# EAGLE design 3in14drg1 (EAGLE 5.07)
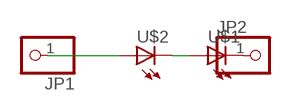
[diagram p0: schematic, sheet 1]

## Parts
JP1  PINHD-1X11X0.4  [1X01]
JP2  PINHD-1X11X0.4  [1X01]
U$1  LEDSMT1206  [1206]
U$2  LEDSMT1206  [1206]

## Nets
N$1: JP1.1 U$2.A
N$3: U$1.A U$2.C
N$4: JP2.1 U$1.C

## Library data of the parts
JP1 JP2 = pinhead:PINHD-1X1: PIN HEADER
U$1 U$2 = led(2):LED: LED

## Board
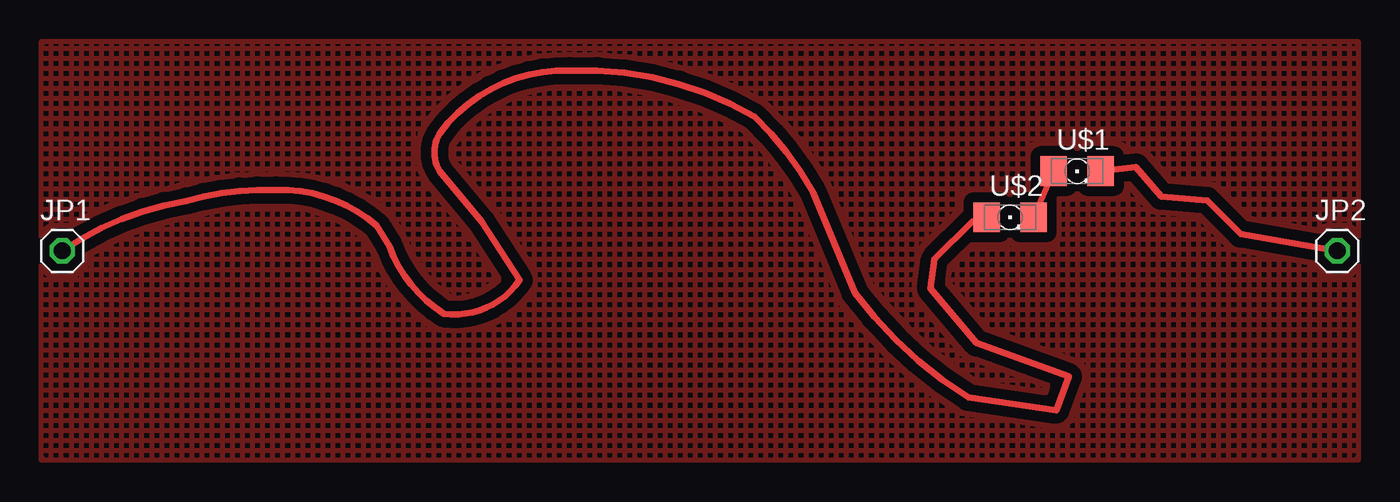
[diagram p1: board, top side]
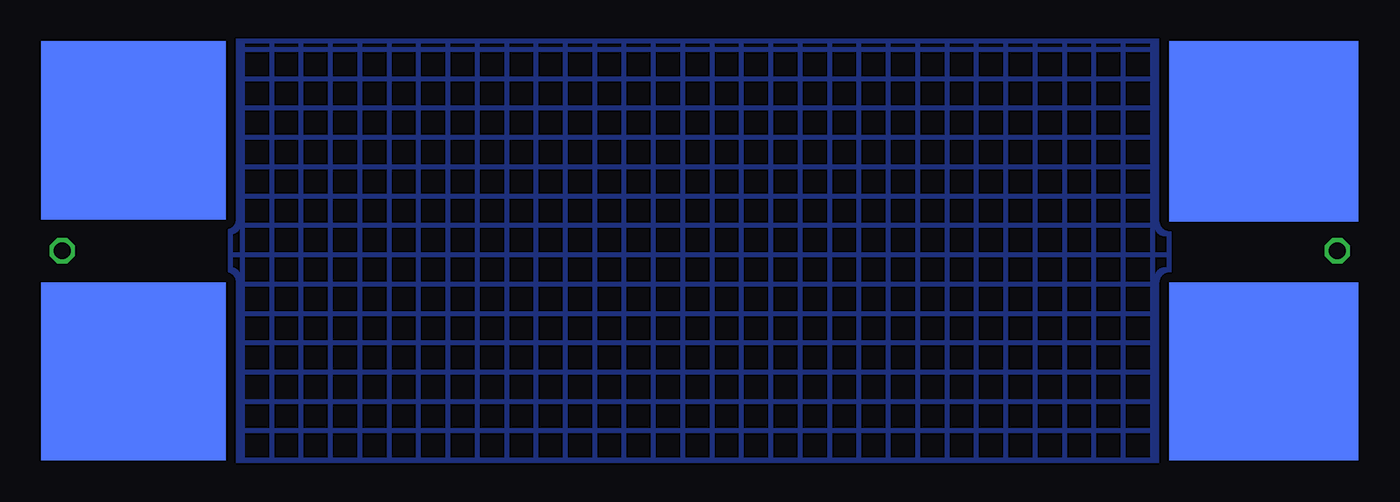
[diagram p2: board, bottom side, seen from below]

No outline drawn. Coordinates in mm, seen from the top.
Copper layers (1*16): Top 0.035mm / dielectric 1.5mm / Bottom 0.035mm
Design rules "default": minimum track width 10mil, minimum drill 24mil, track to track 8mil, track to pad 8mil, pad to pad 8mil, via to via 8mil, smd to smd 8mil, copper to edge 40mil, drill to drill 8mil, minimum pad ring 10mil, minimum via ring 8mil, stop-mask expansion 4mil, vias tented up to drill 0mil, thermal gap 10mil

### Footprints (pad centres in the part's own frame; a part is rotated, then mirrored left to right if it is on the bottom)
1X01 = drill 1.016 octagon: 1 0,0
1206 = smd 1.6 x 1.803: A -1.422,0; C 1.422,0

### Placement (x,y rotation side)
JP1  1.27,12.7 0 top
JP2  78.49,12.7 0 top
U$1  62.74,17.53 0 top
U$2  58.67,14.73 0 top

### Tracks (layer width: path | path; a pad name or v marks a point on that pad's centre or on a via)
N$1
  Top 0.406: JP1.1 arc-25 8.79,15.72 arc-19 14.2,16.38 arc-43 20.32,14.22 21.08,12.95 arc37 24.38,8.89 arc63 28.96,10.92 26.67,14.48 24.13,17.53 arc-62 24.13,19.81 arc-56 32,23.62 arc-33 43.18,20.83 arc-17 46.74,16.26 49.28,10.16 arc21 56.13,3.81 61.47,3.05 62.23,5.08 56.64,7.11 53.85,10.41 54.1,12.19 56.39,14.48 U$2.A
N$2
  pour Top (isolate 0.61, hatched): 0,25.4 79.76,25.4 79.76,0 0,0
  pour Bottom (isolate 0.61, hatched): 11.43,25.4 68.33,25.4 68.33,0 11.43,0
N$3
  Top 0.406: U$2.C U$1.A
N$4
  Top 0.406: JP2.1 72.64,13.72 70.61,15.75 67.82,16 66.29,17.78 U$1.C
(copper drawn outside any net)
  shapes: Bottom area x4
